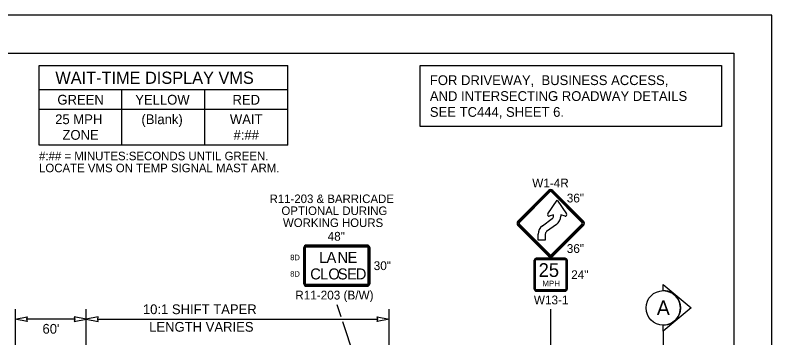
# Model space of a CAD drawing. Extents: x 99976 to 100136, y 99905 to 100011.
# Drawn here: x 100049.86 to 100056.06, y 99948.05 to 99950.69 of the extents above; entities that cross this region are included whole.
import ezdxf

# ---------------------------------------------------------------- set-up
doc = ezdxf.new("R2010")
doc.units = 0
for name, color, linetype in [('SH_GI_PlotLimits', 7, 'Continuous'), ('SH_GI_SheetBorder', 7, 'Continuous'), ('SH_TI_Tables', 7, 'Continuous'), ('SH_TI_WZSectionCut', 7, 'Continuous'), ('TR_SN_ConstructionSigns', 7, 'Continuous'), ('TR_WZ_PortableChangeMessageSign', 7, 'Continuous'), ('TR_WZ_WorkZoneDetails', 7, 'Continuous'), ('TR_WZ_WorkZoneTextCurrent', 7, 'Continuous')]:
    doc.layers.add(name, color=color, linetype=linetype)

msp = doc.modelspace()

# ---------------------------------------------------------------- linework, layer by layer
at = {"layer": 'SH_GI_PlotLimits'}
msp.add_lwpolyline([(100039.0625, 99939.6875), (100056.0625, 99939.6875), (100056.0625, 99950.6875), (100039.0625, 99950.6875)], close=True, dxfattribs=at)
at = {"layer": 'SH_GI_SheetBorder'}
for p, q in [((100040, 99950.375), (100055.75, 99950.375)), ((100055.75, 99950.375), (100055.75, 99940))]:
    msp.add_line(p, q, dxfattribs=at)
at = {"layer": 'SH_TI_Tables'}
msp.add_lwpolyline([(100053.1782, 99950.275), (100055.65, 99950.275), (100055.65, 99949.775), (100053.1782, 99949.775)], close=True, dxfattribs=at)
at = {"layer": 'SH_TI_WZSectionCut'}
for p, q in [((100055.1718, 99948.4317), (100055.1718, 99948.4816)), ((100055.1718, 99948.4816), (100055.4, 99948.2904)), ((100055.4, 99948.2904), (100055.1718, 99948.0993)), ((100055.1718, 99948.0993), (100055.1718, 99948.1492)), ((100055.1718, 99948.0993), (100055.1718, 99946.0193))]:
    msp.add_line(p, q, dxfattribs=at)
msp.add_circle((100055.1718, 99948.2904), 0.1412, dxfattribs=at)
msp.add_arc((100055.1718, 99948.2904), 0.1412, 269.99779, 90.00221, dxfattribs=at)
at = {"layer": 'TR_SN_ConstructionSigns'}
for p, q in [((100054.2311, 99949.2517), (100053.9805, 99949.0011)), ((100054.236, 99949.2467), (100053.9855, 99948.9961)), ((100053.9924, 99948.9892), (100054.243, 99949.2398)), ((100054.2549, 99949.2398), (100054.5055, 99948.9892)), ((100054.5125, 99948.9961), (100054.2619, 99949.2467)), ((100054.5174, 99949.0011), (100054.2669, 99949.2517)), ((100054.2246, 99949.0601), (100054.3021, 99949.173)), ((100054.3021, 99949.173), (100054.3795, 99949.0601)), ((100054.1806, 99948.9631), (100054.262, 99949.0217)), ((100054.2725, 99949.0532), (100054.2366, 99949.0417)), ((100054.2725, 99949.0423), (100054.2725, 99949.0532)), ((100054.3675, 99949.0417), (100054.3316, 99949.0532)), ((100054.3316, 99949.0532), (100054.3316, 99949.0423)), ((100053.9805, 99948.9653), (100054.2311, 99948.7147)), ((100053.9855, 99948.9703), (100054.236, 99948.7197)), ((100054.243, 99948.7267), (100053.9924, 99948.9772)), ((100054.2966, 99948.9738), (100054.2152, 99948.9151)), ((100054.5055, 99948.9772), (100054.2549, 99948.7267)), ((100054.2619, 99948.7197), (100054.5125, 99948.9703)), ((100054.2669, 99948.7147), (100054.5174, 99948.9653)), ((100054.1456, 99948.844), (100054.1456, 99948.8946)), ((100054.2047, 99948.8946), (100054.2047, 99948.844)), ((100054.2047, 99948.844), (100054.1456, 99948.844)), ((100052.2247, 99948.4884), (100052.2247, 99948.7837)), ((100052.2247, 99948.7837), (100052.2247, 99948.4884)), ((100052.2247, 99948.7837), (100052.2247, 99948.4884)), ((100052.2303, 99948.7837), (100052.2303, 99948.4884)), ((100052.2388, 99948.4884), (100052.2388, 99948.7837)), ((100052.2458, 99948.8048), (100052.7436, 99948.8048)), ((100052.7436, 99948.8048), (100052.2458, 99948.8048)), ((100052.7436, 99948.8048), (100052.2458, 99948.8048)), ((100052.7436, 99948.7992), (100052.2458, 99948.7992)), ((100052.2458, 99948.7907), (100052.7436, 99948.7907)), ((100052.7506, 99948.7837), (100052.7506, 99948.4884)), ((100052.7591, 99948.4884), (100052.7591, 99948.7837)), ((100052.7647, 99948.7837), (100052.7647, 99948.4884)), ((100052.7647, 99948.4884), (100052.7647, 99948.7837)), ((100052.7647, 99948.4884), (100052.7647, 99948.7837)), ((100054.114, 99948.4442), (100054.114, 99948.6804)), ((100054.114, 99948.6804), (100054.114, 99948.4442)), ((100054.114, 99948.6804), (100054.114, 99948.4442)), ((100054.1182, 99948.6804), (100054.1182, 99948.4442)), ((100054.1252, 99948.4442), (100054.1252, 99948.6804)), ((100054.1308, 99948.6973), (100054.3671, 99948.6973)), ((100054.3671, 99948.6973), (100054.1308, 99948.6973)), ((100054.3671, 99948.6973), (100054.1308, 99948.6973)), ((100054.3671, 99948.6931), (100054.1308, 99948.6931)), ((100054.1308, 99948.6861), (100054.3671, 99948.6861)), ((100054.3727, 99948.6804), (100054.3727, 99948.4442)), ((100054.3797, 99948.4442), (100054.3797, 99948.6804)), ((100054.384, 99948.6804), (100054.384, 99948.4442)), ((100054.384, 99948.4442), (100054.384, 99948.6804)), ((100054.384, 99948.4442), (100054.384, 99948.6804)), ((100052.7436, 99948.4814), (100052.2458, 99948.4814)), ((100052.2458, 99948.4729), (100052.7436, 99948.4729)), ((100052.7436, 99948.4673), (100052.2458, 99948.4673)), ((100052.2458, 99948.4673), (100052.7436, 99948.4673)), ((100052.2458, 99948.4673), (100052.7436, 99948.4673)), ((100054.3671, 99948.4386), (100054.1308, 99948.4386)), ((100054.1308, 99948.4315), (100054.3671, 99948.4315)), ((100054.3671, 99948.4273), (100054.1308, 99948.4273)), ((100054.1308, 99948.4273), (100054.3671, 99948.4273)), ((100054.1308, 99948.4273), (100054.3671, 99948.4273))]:
    msp.add_line(p, q, dxfattribs=at)
for centre, radius, start, end in [((100054.249, 99949.2338), 0.0253, 45, 135), ((100054.249, 99949.2338), 0.0183, 45, 135), ((100054.249, 99949.2338), 0.00844, 45, 135), ((100054.2346, 99949.0535), 0.012, 146.3859, 280.04666), ((100054.2472, 99949.0423), 0.0253, 305.79396, 0.00002), ((100054.2472, 99949.0423), 0.0844, 305.79396, 0.00002), ((100054.3696, 99949.0535), 0.012, 259.95336, 33.61411), ((100053.9984, 99948.9832), 0.0253, 135, 225.00001), ((100053.9984, 99948.9832), 0.0183, 135, 225.00001), ((100053.9984, 99948.9832), 0.00844, 135, 225.00001), ((100054.23, 99948.8946), 0.0844, 125.79393, 180.00001), ((100054.4995, 99948.9832), 0.00844, 315.00002, 45), ((100054.4995, 99948.9832), 0.0183, 315.00002, 45), ((100054.4995, 99948.9832), 0.0253, 315.00001, 45.00001), ((100054.23, 99948.8946), 0.0253, 125.79393, 180.00001), ((100052.2458, 99948.7837), 0.0211, 90, 180), ((100052.2458, 99948.7837), 0.0211, 90, 180), ((100052.2458, 99948.7837), 0.0211, 90, 180), ((100052.2458, 99948.7837), 0.0155, 90, 180.00001), ((100052.2458, 99948.7837), 0.00703, 90, 180.00001), ((100052.7436, 99948.7837), 0.0211, 0, 90), ((100052.7436, 99948.7837), 0.0211, 0, 90), ((100052.7436, 99948.7837), 0.0211, 0, 90), ((100052.7436, 99948.7837), 0.0155, 0, 90), ((100052.7436, 99948.7837), 0.00703, 0, 90), ((100054.249, 99948.7326), 0.0253, 225.00001, 315.00001), ((100054.249, 99948.7326), 0.0183, 225.00001, 315.00002), ((100054.249, 99948.7326), 0.00844, 225.00001, 315.00002), ((100054.1308, 99948.6804), 0.0169, 90, 180), ((100054.1308, 99948.6804), 0.0169, 90, 180), ((100054.1308, 99948.6804), 0.0169, 90, 180), ((100054.1308, 99948.6804), 0.0127, 90, 180.00001), ((100054.1308, 99948.6804), 0.00562, 90, 180.00001), ((100054.3671, 99948.6804), 0.0169, 0, 90), ((100054.3671, 99948.6804), 0.0169, 0, 90), ((100054.3671, 99948.6804), 0.0169, 0, 90), ((100054.3671, 99948.6804), 0.0127, 0, 90), ((100054.3671, 99948.6804), 0.00562, 0, 90), ((100052.2458, 99948.4884), 0.0211, 180, 270.00001), ((100052.2458, 99948.4884), 0.0211, 180, 270.00001), ((100052.2458, 99948.4884), 0.0211, 180, 270.00001), ((100052.2458, 99948.4884), 0.0155, 180.00001, 270), ((100052.2458, 99948.4884), 0.00703, 180.00001, 270), ((100052.7436, 99948.4884), 0.0155, 270, 0.00001), ((100052.7436, 99948.4884), 0.00703, 270, 0.00001), ((100052.7436, 99948.4884), 0.0211, 270.00001, 0.00001), ((100052.7436, 99948.4884), 0.0211, 270.00001, 0.00001), ((100052.7436, 99948.4884), 0.0211, 270.00001, 0.00001), ((100054.1308, 99948.4442), 0.0169, 180, 270.00001), ((100054.1308, 99948.4442), 0.0169, 180, 270.00001), ((100054.1308, 99948.4442), 0.0169, 180, 270.00001), ((100054.1308, 99948.4442), 0.0127, 180.00001, 270), ((100054.1308, 99948.4442), 0.00562, 180.00001, 270), ((100054.3671, 99948.4442), 0.0169, 270.00001, 0.00001), ((100054.3671, 99948.4442), 0.0169, 270.00001, 0.00001), ((100054.3671, 99948.4442), 0.0127, 270, 0.00001), ((100054.3671, 99948.4442), 0.00562, 270, 0.00001), ((100054.3671, 99948.4442), 0.0169, 270.00001, 0.00001)]:
    msp.add_arc(centre, radius, start, end, dxfattribs=at)
at = {"layer": 'TR_WZ_PortableChangeMessageSign'}
for p, q in [((100050.0535, 99950.275), (100052.0935, 99950.275)), ((100050.0535, 99949.6227), (100050.0535, 99950.275)), ((100052.0935, 99949.6227), (100052.0935, 99950.275)), ((100052.0935, 99950.075), (100050.0535, 99950.075)), ((100050.7335, 99949.6227), (100050.7335, 99950.075)), ((100051.4135, 99949.6227), (100051.4135, 99950.075)), ((100050.7335, 99949.915), (100050.0535, 99949.915)), ((100051.4135, 99949.915), (100050.7335, 99949.915)), ((100052.0935, 99949.915), (100051.4135, 99949.915)), ((100052.0935, 99949.6227), (100050.0535, 99949.6227))]:
    msp.add_line(p, q, dxfattribs=at)
at = {"layer": 'TR_WZ_WorkZoneDetails'}
for p, q in [((100049.8576, 99948.2793), (100049.8576, 99946.9093)), ((100050.4406, 99947.5393), (100050.4406, 99948.2793)), ((100052.4947, 99948.3193), (100052.5282, 99948.2193)), ((100052.9246, 99946.5193), (100052.9246, 99948.2793)), ((100054.2469, 99948.2793), (100054.2469, 99946.6926)), ((100050.3469, 99948.1993), (100049.9513, 99948.1993)), ((100050.5343, 99948.1993), (100052.8309, 99948.1993)), ((100052.5416, 99948.1793), (100052.7264, 99947.6273))]:
    msp.add_line(p, q, dxfattribs=at)
for points in [[(100049.8576, 99948.1993), (100049.9558, 99948.2186), (100049.9513, 99948.1993), (100049.9558, 99948.18)], [(100050.4406, 99948.1993), (100050.3423, 99948.2186), (100050.3469, 99948.1993), (100050.3423, 99948.18)], [(100050.4406, 99948.1993), (100050.5389, 99948.18), (100050.5343, 99948.1993), (100050.5389, 99948.2186)], [(100052.9246, 99948.1993), (100052.8263, 99948.18), (100052.8309, 99948.1993), (100052.8263, 99948.2186)]]:
    msp.add_lwpolyline(points, close=True, dxfattribs=at)

# ---------------------------------------------------------------- texts
at = {"layer": 'SH_TI_Tables'}
for s, p in [('FOR DRIVEWAY,  BUSINESS ACCESS, ', (100053.2582, 99950.115)), ('AND INTERSECTING ROADWAY DETAILS', (100053.2582, 99949.985)), ('SEE TC444, SHEET 6.', (100053.2582, 99949.855))]:
    msp.add_text(s, height=0.08, rotation=360, dxfattribs=at).set_placement(p)
at = {"layer": 'SH_TI_WZSectionCut'}
msp.add_text('A', height=0.12, rotation=359.99005, dxfattribs=at).set_placement((100055.1189, 99948.2313))
at = {"layer": 'TR_SN_ConstructionSigns'}
for s, height, p in [('W1-4R', 0.072, (100054.0975, 99949.2771)), ('8D', 0.045, (100052.1131, 99948.6811)), ('L', 0.09, (100052.3498, 99948.6586)), ('A', 0.09, (100052.411, 99948.6586)), ('N', 0.09, (100052.501, 99948.6586)), ('E', 0.09, (100052.5838, 99948.6586)), ('25', 0.1125, (100054.15, 99948.544)), ('8D', 0.045, (100052.1131, 99948.5461)), ('C', 0.09, (100052.2773, 99948.5236)), ('L', 0.09, (100052.3583, 99948.5236)), ('O', 0.09, (100052.4258, 99948.5236)), ('S', 0.09, (100052.5032, 99948.5236)), ('E', 0.09, (100052.5797, 99948.5236)), ('D', 0.09, (100052.6508, 99948.5236)), ('M', 0.045, (100054.1817, 99948.4681)), ('P', 0.045, (100054.2357, 99948.4681)), ('H', 0.045, (100054.2798, 99948.4681))]:
    msp.add_text(s, height=height, dxfattribs=at).set_placement(p)
for s, p in [('36"', (100054.381, 99949.154)), ('48"', (100052.4199, 99948.8408)), ('36"', (100054.381, 99948.7404)), ('30"', (100052.7979, 99948.6001)), ('24"', (100054.4172, 99948.5263)), ('R11-203 (B/W)', (100052.1543, 99948.3593)), ('W13-1', (100054.1111, 99948.3193))]:
    msp.add_text(s, height=0.072, rotation=360, dxfattribs=at).set_placement(p)
at = {"layer": 'TR_WZ_PortableChangeMessageSign'}
for s, height, p in [('WAIT-TIME DISPLAY VMS', 0.1, (100050.1873, 99950.125)), ('GREEN', 0.08, (100050.2041, 99949.955)), ('YELLOW', 0.08, (100050.8426, 99949.955)), ('RED', 0.08, (100051.6396, 99949.955)), ('(Blank)', 0.08, (100050.8931, 99949.795)), ('25 MPH', 0.08, (100050.1859, 99949.795)), ('WAIT', 0.08, (100051.6185, 99949.795)), ('ZONE', 0.08, (100050.2456, 99949.667)), ('#:##', 0.08, (100051.6486, 99949.667)), ('#:## = MINUTES:SECONDS UNTIL GREEN.', 0.07, (100050.0535, 99949.4993)), ('LOCATE VMS ON TEMP SIGNAL MAST ARM.', 0.07, (100050.0535, 99949.4013))]:
    msp.add_text(s, height=height, rotation=360, dxfattribs=at).set_placement(p)
at = {"layer": 'TR_WZ_WorkZoneTextCurrent'}
for s, p in [('R11-203 & BARRICADE', (100051.9439, 99949.1488)), ('OPTIONAL DURING', (100052.041, 99949.0508)), ('WORKING HOURS', (100052.0537, 99948.9528))]:
    msp.add_text(s, height=0.07, rotation=360, dxfattribs=at).set_placement(p)
for s, p in [('10:1 SHIFT TAPER', (100050.9051, 99948.2393)), ("60'", (100050.0819, 99948.0791)), ('LENGTH VARIES', (100050.9564, 99948.0953))]:
    msp.add_text(s, height=0.08, dxfattribs=at).set_placement(p)

doc.saveas('drawing.dxf')
